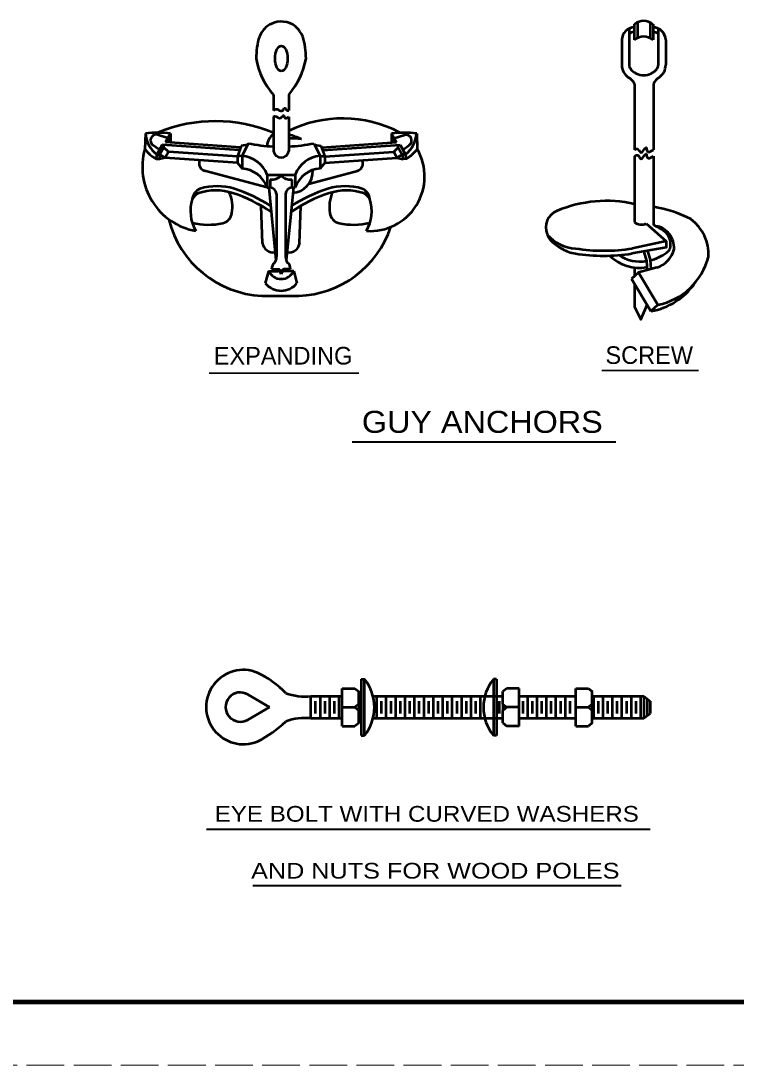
# Model space of a CAD drawing. Extents: x 12366 to 13046, y 9129 to 9570.
# Drawn here: x 12746.6 to 12860.4, y 9129.5 to 9295.6 of the extents above; entities that cross this region are included whole.
import ezdxf
from ezdxf.enums import TextEntityAlignment as Align

# ---------------------------------------------------------------- set-up
doc = ezdxf.new("R2010")
doc.units = 0
doc.linetypes.add('LONG_DASHED', pattern=[7.5, 6, -1.5])
doc.layers.add('1', color=7, linetype='Continuous', lineweight=53)
doc.layers.add('61', color=7, linetype='Continuous', lineweight=35)

msp = doc.modelspace()

# ---------------------------------------------------------------- linework, layer by layer
at = {"layer": '1'}
for p, q in [((12844.194, 9295.103), (12844.194, 9292.603)), ((12844.694, 9295.402), (12844.694, 9292.902)), ((12846.694, 9295.403), (12846.694, 9292.903)), ((12847.194, 9295.103), (12847.194, 9292.603)), ((12843.394, 9294.406), (12843.394, 9288.51)), ((12847.994, 9294.406), (12847.994, 9288.495)), ((12842.194, 9292.603), (12842.194, 9288.603)), ((12849.194, 9292.603), (12849.194, 9288.603)), ((12844.231, 9285.614), (12844.231, 9275.114)), ((12847.231, 9285.614), (12847.231, 9275.114)), ((12786.773, 9283.875), (12786.773, 9281.375)), ((12789.205, 9283.875), (12789.205, 9281.375)), ((12786.773, 9280.375), (12786.773, 9274.875)), ((12789.205, 9280.375), (12789.205, 9274.875)), ((12766.399, 9277.717), (12766.312, 9275.218)), ((12769.969, 9276.943), (12768.314, 9277.512)), ((12770.399, 9277.717), (12769.615, 9276.305)), ((12781.52, 9275.473), (12769.615, 9276.305)), ((12769.969, 9276.943), (12769.969, 9276.281)), ((12770.399, 9277.717), (12770.399, 9276.251)), ((12794.457, 9275.489), (12806.355, 9276.321)), ((12805.579, 9277.717), (12806.355, 9276.321)), ((12805.579, 9277.717), (12805.579, 9276.267)), ((12806.009, 9276.943), (12807.664, 9277.512)), ((12806.009, 9276.943), (12806.009, 9276.297)), ((12809.579, 9277.717), (12809.667, 9275.218)), ((12768.63, 9275.11), (12767.607, 9275.827)), ((12769.06, 9275.884), (12768.201, 9274.337)), ((12781.344, 9275.025), (12769.06, 9275.884)), ((12769.338, 9275.483), (12769.338, 9275.865)), ((12770.057, 9274.788), (12769.338, 9275.483)), ((12770.057, 9274.788), (12769.558, 9273.823)), ((12781.03, 9274.021), (12770.057, 9274.788)), ((12782.648, 9275.875), (12781.658, 9275.736)), ((12782.773, 9276.125), (12781.773, 9274.125)), ((12793.205, 9276.125), (12794.205, 9274.125)), ((12793.33, 9275.875), (12794.32, 9275.736)), ((12794.634, 9275.025), (12806.918, 9275.884)), ((12794.948, 9274.021), (12805.921, 9274.788)), ((12805.921, 9274.788), (12806.64, 9275.483)), ((12805.921, 9274.788), (12806.42, 9273.823)), ((12806.64, 9275.483), (12806.64, 9275.865)), ((12806.918, 9275.884), (12807.778, 9274.337)), ((12807.348, 9275.11), (12808.372, 9275.827)), ((12768.201, 9274.337), (12768.71, 9274.353)), ((12769.558, 9273.823), (12768.584, 9273.598)), ((12769.558, 9273.823), (12768.71, 9274.353)), ((12781.03, 9273.021), (12769.558, 9273.823)), ((12781.773, 9274.125), (12781.03, 9274.021)), ((12781.773, 9274.125), (12781.773, 9272.125)), ((12794.205, 9274.125), (12794.205, 9272.125)), ((12794.205, 9274.125), (12794.948, 9274.021)), ((12794.948, 9273.021), (12806.42, 9273.823)), ((12806.42, 9273.823), (12807.268, 9274.353)), ((12806.42, 9273.823), (12807.394, 9273.598)), ((12807.778, 9274.337), (12807.268, 9274.353)), ((12844.231, 9274.114), (12844.231, 9263.614)), ((12847.231, 9274.114), (12847.231, 9263.106)), ((12785.773, 9269.088), (12775.806, 9271.758)), ((12792.416, 9269.688), (12800.143, 9271.758)), ((12785.773, 9271.125), (12790.205, 9271.125)), ((12785.773, 9271.125), (12785.773, 9269.088)), ((12786.273, 9270.375), (12786.273, 9269.125)), ((12789.705, 9270.375), (12789.705, 9269.125)), ((12790.205, 9271.125), (12790.205, 9269.125)), ((12785.773, 9269.125), (12786.273, 9269.125)), ((12786.023, 9269.125), (12787.178, 9257.569)), ((12787.273, 9268.125), (12787.273, 9258.125)), ((12788.705, 9268.125), (12788.705, 9258.125)), ((12789.955, 9269.125), (12788.801, 9257.569)), ((12789.705, 9269.125), (12790.205, 9269.125)), ((12785.04, 9260.206), (12784.831, 9266.202)), ((12790.938, 9260.206), (12791.148, 9266.202)), ((12846.084, 9263.395), (12849.243, 9260.551)), ((12849.243, 9260.551), (12843.863, 9259.407)), ((12846.288, 9259.03), (12846.727, 9257.596)), ((12844.231, 9256.384), (12844.231, 9255.002)), ((12847.771, 9256.357), (12844.873, 9255.58)), ((12846.727, 9257.596), (12846.805, 9256.098)), ((12785.995, 9255.819), (12785.478, 9253.887)), ((12785.995, 9255.819), (12787.495, 9255.819)), ((12786.489, 9256.14), (12787.489, 9256.14)), ((12789.489, 9256.14), (12788.489, 9256.14)), ((12789.995, 9255.819), (12788.495, 9255.819)), ((12789.995, 9255.819), (12790.513, 9253.887)), ((12844.873, 9255.58), (12843.759, 9254.576)), ((12844.873, 9255.58), (12847.964, 9250.437)), ((12843.759, 9254.576), (12846.849, 9249.433)), ((12784.93, 9251.872), (12790.791, 9251.863)), ((12847.964, 9250.437), (12846.849, 9249.433)), ((12800.735, 9190.913), (12800.735, 9181.913)), ((12800.735, 9190.913), (12801.235, 9190.913)), ((12801.235, 9190.913), (12801.235, 9181.913)), ((12821.789, 9190.913), (12821.789, 9181.913)), ((12822.289, 9190.913), (12821.789, 9190.913)), ((12822.289, 9190.913), (12822.289, 9181.913)), ((12786.161, 9186.445), (12782.697, 9188.445)), ((12797.735, 9189.413), (12799.735, 9189.413)), ((12800.335, 9186.913), (12800.335, 9188.913)), ((12823.899, 9189.431), (12823.299, 9188.931)), ((12823.299, 9186.931), (12823.299, 9188.931)), ((12825.899, 9189.431), (12823.899, 9189.431)), ((12834.899, 9189.431), (12836.899, 9189.431)), ((12836.899, 9189.431), (12837.499, 9188.931)), ((12837.499, 9186.931), (12837.499, 9188.931)), ((12792.735, 9184.663), (12792.735, 9188.163)), ((12792.735, 9188.163), (12797.714, 9188.163)), ((12793.485, 9185.413), (12793.485, 9187.413)), ((12794.235, 9184.663), (12794.235, 9188.163)), ((12794.985, 9185.413), (12794.985, 9187.413)), ((12795.735, 9184.663), (12795.735, 9188.163)), ((12796.485, 9185.413), (12796.485, 9187.413)), ((12797.235, 9184.663), (12797.235, 9188.163)), ((12800.326, 9188.163), (12800.71, 9188.163)), ((12800.335, 9186.913), (12800.335, 9185.913)), ((12802.617, 9188.163), (12823.238, 9188.163)), ((12803.235, 9184.663), (12803.235, 9188.163)), ((12803.985, 9185.413), (12803.985, 9187.413)), ((12804.735, 9184.663), (12804.735, 9188.163)), ((12805.485, 9185.413), (12805.485, 9187.413)), ((12806.235, 9184.663), (12806.235, 9188.163)), ((12806.985, 9185.413), (12806.985, 9187.413)), ((12807.735, 9184.663), (12807.735, 9188.163)), ((12808.485, 9185.413), (12808.485, 9187.413)), ((12809.235, 9184.663), (12809.235, 9188.163)), ((12809.985, 9185.413), (12809.985, 9187.413)), ((12810.735, 9184.663), (12810.735, 9188.163)), ((12811.485, 9185.413), (12811.485, 9187.413)), ((12812.235, 9184.663), (12812.235, 9188.163)), ((12812.985, 9185.413), (12812.985, 9187.413)), ((12813.735, 9184.663), (12813.735, 9188.163)), ((12814.485, 9185.413), (12814.485, 9187.413)), ((12815.235, 9184.663), (12815.235, 9188.163)), ((12815.985, 9185.413), (12815.985, 9187.413)), ((12816.735, 9184.663), (12816.735, 9188.163)), ((12817.485, 9185.413), (12817.485, 9187.413)), ((12818.235, 9184.663), (12818.235, 9188.163)), ((12818.985, 9185.413), (12818.985, 9187.413)), ((12819.735, 9184.663), (12819.735, 9188.163)), ((12822.741, 9185.413), (12822.741, 9187.413)), ((12823.299, 9186.931), (12823.299, 9185.931)), ((12825.831, 9188.163), (12834.855, 9188.163)), ((12826.485, 9185.413), (12826.485, 9187.413)), ((12827.235, 9184.663), (12827.235, 9188.163)), ((12827.985, 9185.413), (12827.985, 9187.413)), ((12828.735, 9184.663), (12828.735, 9188.163)), ((12829.485, 9185.413), (12829.485, 9187.413)), ((12830.235, 9184.663), (12830.235, 9188.163)), ((12830.985, 9185.413), (12830.985, 9187.413)), ((12831.735, 9184.663), (12831.735, 9188.163)), ((12832.485, 9185.413), (12832.485, 9187.413)), ((12833.235, 9184.663), (12833.235, 9188.163)), ((12833.985, 9185.413), (12833.985, 9187.413)), ((12837.448, 9188.163), (12845.735, 9188.163)), ((12837.499, 9186.931), (12837.499, 9185.931)), ((12837.735, 9184.663), (12837.735, 9188.163)), ((12838.485, 9185.413), (12838.485, 9187.413)), ((12839.235, 9184.663), (12839.235, 9188.163)), ((12839.985, 9185.413), (12839.985, 9187.413)), ((12840.735, 9184.663), (12840.735, 9188.163)), ((12841.485, 9185.413), (12841.485, 9187.413)), ((12842.235, 9184.663), (12842.235, 9188.163)), ((12842.985, 9185.413), (12842.985, 9187.413)), ((12843.735, 9184.663), (12843.735, 9188.163)), ((12844.485, 9185.413), (12844.485, 9187.413)), ((12845.235, 9184.663), (12845.235, 9188.163)), ((12845.735, 9188.163), (12845.735, 9184.663)), ((12845.735, 9188.163), (12846.735, 9187.413)), ((12846.235, 9187.788), (12846.235, 9185.038)), ((12846.735, 9187.413), (12846.735, 9185.413)), ((12786.161, 9186.445), (12782.697, 9184.445)), ((12797.735, 9186.413), (12799.735, 9186.413)), ((12800.335, 9183.913), (12800.335, 9185.913)), ((12823.299, 9183.931), (12823.299, 9185.931)), ((12825.899, 9186.431), (12823.899, 9186.431)), ((12834.899, 9186.431), (12836.899, 9186.431)), ((12837.499, 9183.931), (12837.499, 9185.931)), ((12845.735, 9184.663), (12846.735, 9185.413)), ((12792.735, 9184.663), (12797.714, 9184.663)), ((12797.735, 9183.413), (12799.735, 9183.413)), ((12800.335, 9183.913), (12799.735, 9183.413)), ((12800.326, 9184.663), (12800.724, 9184.663)), ((12802.617, 9184.663), (12823.309, 9184.663)), ((12823.299, 9183.931), (12823.899, 9183.431)), ((12825.899, 9183.431), (12823.899, 9183.431)), ((12834.899, 9183.431), (12836.899, 9183.431)), ((12837.499, 9183.931), (12836.899, 9183.431)), ((12837.483, 9184.663), (12845.735, 9184.663)), ((12800.735, 9181.913), (12801.235, 9181.913)), ((12822.289, 9181.913), (12821.789, 9181.913))]:
    msp.add_line(p, q, dxfattribs=at)
at = {"layer": '1', "lineweight": 13}
msp.add_line((12844.231, 9255.066), (12844.231, 9254.871), dxfattribs=at)
at = {"layer": '1', "lineweight": 35}
for p, q in [((12839.039, 9239.975), (12854.414, 9239.975)), ((12776.559, 9239.584), (12800.339, 9239.584))]:
    msp.add_line(p, q, dxfattribs=at)
at = {"layer": '1', "lineweight": 40}
for p, q in [((12799.305, 9228.627), (12841.276, 9228.627)), ((12776.122, 9167.031), (12846.733, 9167.031)), ((12783.477, 9158.091), (12842.093, 9158.091))]:
    msp.add_line(p, q, dxfattribs=at)
at = {"layer": '1'}
for points in [[(12769.338, 9275.483), (12768.71, 9274.353), (12768.584, 9273.598)], [(12781.658, 9275.736), (12781.03, 9274.021), (12781.03, 9273.021), (12781.773, 9272.125)], [(12794.32, 9275.736), (12794.948, 9274.021), (12794.948, 9273.021), (12794.205, 9272.125)], [(12806.64, 9275.483), (12807.268, 9274.353), (12807.394, 9273.598)], [(12768.201, 9274.337), (12768.091, 9273.68), (12768.584, 9273.598)], [(12807.778, 9274.337), (12807.887, 9273.68), (12807.394, 9273.598)], [(12849.243, 9260.551), (12849.243, 9259.551), (12843.826, 9258.596)], [(12845.714, 9258.855), (12846.153, 9257.42), (12846.231, 9255.922)], [(12844.231, 9253.791), (12844.231, 9250.114), (12845.231, 9248.114), (12846.231, 9250.461)], [(12797.735, 9183.413), (12797.735, 9186.413), (12797.735, 9189.413)], [(12799.735, 9189.413), (12800.335, 9188.913), (12800.335, 9186.913), (12799.735, 9186.413), (12800.335, 9185.913)], [(12825.899, 9183.431), (12825.899, 9186.431), (12825.899, 9189.431)], [(12834.899, 9183.431), (12834.899, 9186.431), (12834.899, 9189.431)], [(12823.299, 9186.931), (12823.899, 9186.431), (12823.299, 9185.931)], [(12837.499, 9186.931), (12836.899, 9186.431), (12837.499, 9185.931)], [(12825.867, 9184.663), (12834.855, 9184.663), (12834.89, 9184.663)]]:
    msp.add_lwpolyline(points, dxfattribs=at)
for centre, radius, start, end in [((12788.905, 9291.152), 4.797, 131.96494, 155.64508), ((12787.874, 9291.772), 3.664, 114.18463, 126.44768), ((12788.018, 9291.855), 3.65, 51.67793, 116.77606), ((12787.073, 9291.152), 4.797, 24.35492, 48.03506), ((12844.284, 9292.513), 2.091, 92.45547, 177.54453), ((12845.695, 9293.162), 2.454, 52.29201, 127.70799), ((12847.105, 9292.513), 2.091, 2.45547, 87.54453), ((12795.794, 9289.696), 11.771, 163.03649, 180.34718), ((12780.185, 9289.696), 11.771, 359.65283, 16.96351), ((12844.161, 9292.74), 1.113, 88.28293, 133.52461), ((12845.695, 9290.662), 2.454, 52.29201, 127.70799), ((12847.228, 9292.74), 1.113, 46.47539, 91.71707), ((12795.55, 9291.605), 11.695, 189.74744, 221.3725), ((12780.429, 9291.605), 11.695, 318.6275, 350.25256), ((12844.655, 9288.621), 2.461, 180.43177, 234.62969), ((12844.14, 9288.499), 0.746, 179.14798, 220.24311), ((12845.694, 9289.612), 2.656, 216.91814, 322.98043), ((12847.246, 9288.495), 0.746, 319.75689, 0.85202), ((12846.733, 9288.621), 2.461, 305.37031, 359.56823), ((12842.361, 9284.745), 2.062, 24.94304, 65.05696), ((12849.039, 9284.868), 1.956, 116.76572, 157.56298), ((12777.538, 9255.698), 23.957, 67.32753, 112.30219), ((12797.801, 9260.679), 19.427, 62.24214, 116.49544), ((12768.399, 9258.664), 19.158, 84.00757, 95.99243), ((12771.304, 9278.161), 4.925, 185.18056, 230.94579), ((12768.136, 9276.596), 0.933, 78.96142, 235.46809), ((12788.487, 9275.468), 2.756, 128.46984, 175.06692), ((12785.756, 9265.222), 12.786, 64.65247, 74.23543), ((12789.622, 9267.179), 9.732, 80.48984, 92.29918), ((12807.579, 9258.664), 19.158, 84.00757, 95.99243), ((12807.813, 9276.584), 0.941, 306.45493, 99.11556), ((12804.674, 9278.161), 4.925, 309.05421, 354.81944), ((12776.245, 9272.372), 10.333, 164.01359, 259.79898), ((12771.056, 9278.91), 6.012, 217.89069, 240.44911), ((12789.093, 9310.434), 34.887, 259.56289, 266.18708), ((12787.989, 9275.12), 1.24, 191.39485, 348.60515), ((12786.885, 9310.434), 34.887, 273.81292, 280.43711), ((12802.145, 9270.871), 8.688, 266.16365, 30.02378), ((12804.922, 9278.91), 6.012, 299.55089, 322.10931), ((12776.217, 9272.978), 1.287, 158.99371, 251.37679), ((12781.444, 9269.519), 4.618, 20.35078, 85.90942), ((12794.535, 9269.519), 4.618, 94.09058, 159.64922), ((12799.732, 9272.978), 1.287, 288.62321, 21.00629), ((12781.444, 9267.519), 4.618, 20.35078, 85.90942), ((12789.59, 9271.679), 3.439, 273.98395, 2.60406), ((12794.535, 9267.519), 4.618, 94.09058, 159.64922), ((12786.494, 9272.383), 2.02, 263.73433, 317.75599), ((12789.485, 9272.383), 2.02, 222.24401, 276.26567), ((12775.96, 9267.002), 2.114, 115.12547, 173.42944), ((12775.776, 9266.274), 2.147, 116.11742, 153.15373), ((12777.581, 9259.649), 8.985, 72.17801, 107.82199), ((12777.812, 9259.497), 9.812, 73.72458, 106.27542), ((12775.036, 9266.055), 5.217, 348.82631, 26.25382), ((12773.044, 9245.754), 23.601, 55.49077, 72.01683), ((12773.044, 9245.754), 24.351, 56.96697, 72.01675), ((12786.141, 9267.993), 1.14, 6.66371, 83.33629), ((12789.838, 9267.993), 1.14, 96.66371, 173.33629), ((12802.934, 9245.754), 23.601, 107.98317, 124.50923), ((12802.934, 9245.754), 24.351, 107.98325, 123.03303), ((12798.166, 9259.497), 9.812, 73.72458, 106.27542), ((12798.398, 9259.649), 8.985, 72.17801, 107.82199), ((12800.888, 9266.055), 5.217, 153.74618, 191.17369), ((12800.019, 9267.002), 2.114, 6.57056, 64.87453), ((12800.202, 9266.274), 2.147, 26.84627, 63.88258), ((12779.801, 9265.347), 6.237, 162.29086, 210.27517), ((12796.177, 9265.347), 6.237, 329.72483, 17.70914), ((12839.788, 9246.396), 20.575, 77.48956, 112.53539), ((12778.328, 9265.227), 1.835, 282.14771, 354.26068), ((12797.596, 9265.227), 1.835, 185.73932, 257.85229), ((12833.014, 9262.727), 2.894, 112.56326, 201.22601), ((12843.8, 9245.386), 20.932, 63.12438, 80.5666), ((12785.785, 9268.045), 16.196, 194.44102, 266.97322), ((12776.432, 9273.976), 10.787, 256.06592, 282.21618), ((12799.493, 9273.976), 10.787, 257.78382, 283.93408), ((12845.312, 9264.813), 1.615, 227.92906, 298.55891), ((12845.18, 9257.364), 6.097, 47.97836, 70.34854), ((12848.983, 9258.452), 7.038, 357.06801, 53.01462), ((12790.14, 9268.045), 16.196, 272.30306, 341.28411), ((12881.536, 9285.635), 56.546, 205.06602, 205.618), ((12835.249, 9265.976), 6.58, 221.76894, 266.63849), ((12833.116, 9262.618), 2.936, 205.89722, 222.96556), ((12847.466, 9260.341), 2.601, 60.03867, 86.11071), ((12846.814, 9259.408), 3.736, 37.20204, 58.52155), ((12847.303, 9260.078), 2.67, 345.49101, 42.81927), ((12846.781, 9259.441), 3.743, 358.21611, 36.4931), ((12786.74, 9260.519), 1.729, 186.64556, 280.42286), ((12789.238, 9260.519), 1.729, 259.57714, 353.35444), ((12835.93, 9265.675), 7.086, 225.54603, 243.17205), ((12785.154, 9258.202), 2.121, 329.93461, 357.90459), ((12790.825, 9258.202), 2.121, 182.09541, 210.06539), ((12835.718, 9264.341), 5.814, 239.10628, 261.18034), ((12839.326, 9287.625), 29.375, 261.18821, 278.81179), ((12839.363, 9288.436), 29.375, 261.18821, 278.81179), ((12845.109, 9263.38), 7.051, 226.52134, 278.94966), ((12845.109, 9263.38), 6.051, 235.85618, 279.93742), ((12845.092, 9264.503), 7.161, 282.93456, 306.7285), ((12846.519, 9260.276), 4.115, 287.7219, 346.62294), ((12845.819, 9260.75), 10.534, 281.74498, 345.38421), ((12848.045, 9260.345), 2.067, 310.05064, 333.08561), ((12787.741, 9256.139), 1.252, 126.91323, 179.95667), ((12788.237, 9256.139), 1.252, 0.04333, 53.08677), ((12787.995, 9256.794), 2.225, 205.98923, 334.01077), ((12787.376, 9255.527), 0.623, 10.44919, 79.5508), ((12787.382, 9255.206), 0.623, 10.44919, 79.5508), ((12788.602, 9255.527), 0.623, 100.4492, 169.55081), ((12788.608, 9255.206), 0.623, 100.4492, 169.55081), ((12787.995, 9255.933), 3.244, 219.10281, 320.89719), ((12845.075, 9259.869), 10.586, 279.6497, 325.48694), ((12781.976, 9186.452), 5.913, 67.37581, 292.62419), ((12777.646, 9178.067), 15.337, 43.69833, 64.49446), ((12795.707, 9186.413), 7.128, 320.85375, 39.14625), ((12827.317, 9186.413), 7.128, 140.85375, 219.14625), ((12781.495, 9186.445), 2.334, 58.9871, 301.0129), ((12791.923, 9197.92), 9.791, 250.99574, 274.75423), ((12775.987, 9197.394), 18.364, 296.74116, 313.96028), ((12791.923, 9174.918), 9.791, 85.24577, 109.00426)]:
    msp.add_arc(centre, radius, start, end, dxfattribs=at)
msp.add_ellipse((12788.023, 9289.625), major_axis=(0, -2), ratio=0.5, dxfattribs=at)
for points in [[(12786.773, 9281.375), (12787.155, 9281.579), (12787.554, 9281.454), (12788.253, 9281.355), (12788.577, 9281.754), (12788.976, 9281.38), (12789.205, 9281.375)], [(12786.773, 9280.375), (12786.98, 9280.444), (12787.953, 9280.169), (12788.377, 9280.544), (12788.602, 9280.169), (12789.205, 9280.375)], [(12844.231, 9275.114), (12844.78, 9275.228), (12845.268, 9274.667), (12846.073, 9275.448), (12846.244, 9274.886), (12847.231, 9275.114)], [(12844.231, 9274.114), (12844.78, 9274.228), (12845.268, 9273.667), (12846.073, 9274.448), (12846.244, 9273.886), (12847.231, 9274.114)]]:
    msp.add_spline(points, degree=3, dxfattribs=at)
at = {"layer": '61', "lineweight": 158}
msp.add_line((13035.052, 9139.493), (12395.992, 9139.513), dxfattribs=at)
at = {"layer": '61', "linetype": 'LONG_DASHED', "lineweight": 13}
msp.add_line((13045.992, 9129.513), (12365.932, 9129.493), dxfattribs=at)

# ---------------------------------------------------------------- texts
at = {"layer": '1'}
for s, p in [('EXPANDING', (12788.302, 9240.948)), ('SCREW', (12846.574, 9241.045))]:
    msp.add_text(s, height=2.8, dxfattribs=at).set_placement(p, align=Align.CENTER)
for s, height, width, p in [('GUY ANCHORS', 3.5, 1.1, (12820.008, 9230.077)), ('EYE BOLT WITH CURVED WASHERS', 2.5, 1.15, (12811.172, 9168.218)), ('AND NUTS FOR WOOD POLES', 2.5, 1.2, (12812.529, 9159.165))]:
    msp.add_text(s, height=height, dxfattribs=dict(at, width=width)).set_placement(p, align=Align.CENTER)

doc.saveas('drawing.dxf')
